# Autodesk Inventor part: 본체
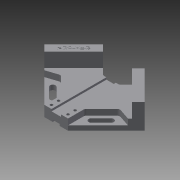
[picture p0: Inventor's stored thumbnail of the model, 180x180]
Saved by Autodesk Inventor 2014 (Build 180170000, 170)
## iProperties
Created: 2019-04
Part Number: 본체
Material: Generic
Document SubType Name: Modeling
Designer: kh
Density: 1 g/cm^3
Appearance: Default
Mass: 222.781 g
Surface Area: 426.536 cm^2
Volume: 222.781 cm^3
Author: kh
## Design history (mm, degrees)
sketch "Sketch1"
  geometry: L1 (0, 84.853)-(-84.853, 0); L2 (-84.853, 0)-(0, -84.853); L3 (0, -84.853)-(84.853, 0); L4 (84.853, 0)-(0, 84.853); L5 (-84.853, 0)-(84.853, 0); L6 (0, 84.853)-(0, -84.853); 3 further points
  constraints: 12 end point, 2 coincident, 2 midpoint, 1 horizontal, 1 perpendicular
  dimensions: "d0" = 120 distance of L1.start L1.end; "d1" = 120 distance of L3.end L1.start; "d2" = 120 distance of L2.end L3.end; "d3" = 120 distance of L1.end L2.end
extrude "Extrusion1" new body sketch "Sketch1" distance "d4" = 18; taper "d5" = 0 deg
sketch "Sketch2"
  geometry: L1 (-8, 18)-(8, 18); L2 (8, 18)-(8, 14.5); L3 (8, 14.5)-(-8, 14.5); L4 (-8, 14.5)-(-8, 18); L5 (-6, 0)-(6, 0); L6 (6, 0)-(6, 3); L7 (6, 3)-(-6, 3); L8 (-6, 3)-(-6, 0); L9 (0, 18)-(-84.853, 18) reference; 2 further points
  constraints: 16 end point, 4 parallel, 2 horizontal, 2 midpoint, 2 perpendicular, 1 coincident
  dimensions: "d6" = 16 distance of L2.end L3.end; "d7" = 3.5 distance of L1.end L2.end; "d8" = 12 distance of L7.end L6.end; "d9" = 3 distance of L6.end L5.end
extrude "Extrusion2" cut sketch "Sketch2" stored distance "d10" = 0; taper "d11" = 0 deg
sketch "Sketch3"
  geometry: L1 (-25, -64.853)-(25, -64.853); L2 (25, -64.853)-(25, -84.853); L3 (25, -84.853)-(-25, -84.853); L4 (-25, -84.853)-(-25, -64.853); L5 (-8, 76.853)-(-84.853, 0) reference; L6 (84.853, 0)-(8, 76.853) reference; L7 (0, 84.853)-(-35.355, 49.497); L8 (-35.355, 49.497)-(0, 14.142); L9 (0, 14.142)-(35.355, 49.497); L10 (35.355, 49.497)-(0, 84.853); L11 (0, -64.853)-(0, 28.147); L12 (0, 28.147)-(14.005, 28.147); L13 (0, 28.147)-(-14.005, 28.147); 3 further points
  constraints: 22 end point, 5 parallel, 3 perpendicular, 3 point on line, 2 midpoint, 1 coincident, 1 collinear, 1 horizontal
  dimensions: "d12" = 20 distance of L1.end L2.end; "d13" = 50 distance of L2.end L3.end; "d14" = 50 distance of L7.start L7.end; "d15" = 50 distance of L8.end L7.end; "d16" = 93 distance of L11.start L11.end
extrude "Extrusion3" cut sketch "Sketch3" stored distance "d17" = 18; taper "d18" = 0 deg
sketch "Sketch4"
  geometry: L1 (84.853, 0)-(35.355, 49.497) reference; L2 (35.355, 49.497)-(84.853, 0); L3 (84.853, 0)-(74.246, -10.607); L4 (74.246, -10.607)-(24.749, 38.891); L5 (24.749, 38.891)-(35.355, 49.497); L6 (-35.355, 49.497)-(-84.853, 0) reference; L7 (-35.355, 49.497)-(-84.853, 0); L8 (-84.853, 0)-(-74.246, -10.607); L9 (-74.246, -10.607)-(-24.749, 38.891); L10 (-24.749, 38.891)-(-35.355, 49.497); 1 further point
  constraints: 16 end point, 6 equal length, 2 perpendicular
  dimensions: "d19" = 15 distance of L1.start L3.end; "d20" = 15 distance of L8.end L6.end
extrude "Extrusion4" join sketch "Sketch4" distance "d21" = 24; taper "d22" = 0 deg
sketch "Sketch5"
  geometry: L1 (-74.246, -10.607)-(-20, -64.853) reference; L2 (-8, 28.147)-(-14.005, 28.147) reference; L3 (-14.005, 28.147)-(-24.749, 38.891) reference; L4 (-20, -64.853)-(-20, -36.569); L5 (-20, -36.569)-(-49.497, -7.071); L6 (-49.497, -7.071)-(-70.711, -14.142); L7 (-84.853, 0)-(-20, -64.853) reference; L8 (-35.355, 49.497)-(-84.853, 0) reference; L9 (0, 0)-(0, 15.349); L10 (-20, -64.853)-(-70.711, -14.142); L11 (20, -64.853)-(70.711, -14.142); L12 (49.497, -7.071)-(70.711, -14.142); L13 (20, -36.569)-(49.497, -7.071); L14 (20, -64.853)-(20, -36.569)
  constraints: 18 end point, 4 symmetric about line, 2 parallel, 1 collinear, 1 perpendicular, 1 point on line
  dimensions: "d25" = 20 distance from line of L1 L5.end; "d26" = 20 distance of L6.end L7.start; "d27" = 30 distance from line of L8 L5.end
extrude "Extrusion5" cut sketch "Sketch5" distance "d28" = 10; taper "d29" = 0 deg
sketch "Sketch6"
  geometry: L1 (-20, -36.569)-(-20, -64.853) reference; L2 (-20, -64.853)-(-70.711, -14.142) reference; L3 (-35.355, 49.497)-(-84.853, 0) reference; L4 (-84.853, 0)-(-20, -64.853) reference; L5 (-49.497, -21.213)-(-32.527, -38.184); L6 (-52.679, -24.395)-(-35.709, -41.366); L7 (-29.345, -35.002)-(-46.315, -18.031); L8 (0, 0)-(0, 13.458); L9 (29.345, -35.002)-(46.315, -18.031); L10 (52.679, -24.395)-(35.709, -41.366); A1 r 4.5 centre (-49.497, -21.213) between (-46.315, -18.031) and (-52.679, -24.395); A2 r 4.5 centre (-32.527, -38.184) between (-35.709, -41.366) and (-29.345, -35.002); A3 r 4.5 centre (49.497, -21.213) between (52.679, -24.395) and (46.315, -18.031); A4 r 4.5 centre (32.527, -38.184) between (29.345, -35.002) and (35.709, -41.366); 1 further point
  constraints: 14 end point, 8 point on circle, 6 symmetric about line, 4 centre point, 4 tangent, 3 parallel, 1 midpoint, 2 other
  dimensions: "d30" = 9 diameter of A2; "d31" = 24 distance of L5.start L5.end; "d32" = 40 distance from line of L3 L5.start; "d33" = 10 distance from line of L2 L5.start
extrude "Extrusion6" cut sketch "Sketch6" stored distance "d34" = 10; taper "d35" = 0 deg
sketch "Sketch7"
  geometry: L1 (6, -64.853)-(20, -64.853) reference; L2 (-14, -46.853)-(14, -46.853); L3 (14, -46.853)-(14, -58.853); L4 (14, -58.853)-(-14, -58.853); L5 (-14, -58.853)-(-14, -46.853); 6 further points
  constraints: 8 end point, 4 coincident, 2 parallel, 1 horizontal, 1 midpoint, 1 perpendicular, 1 vertical alignment
  dimensions: "d36" = 28 distance of L3.end L4.end; "d37" = 12 distance of L2.end L3.end; "d38" = 6 distance between parallel lines of L1 L4
hole "Hole1" sketch "Sketch7" at (-14, -46.853), (-14, -58.853), (14, -58.853), (14, -46.853) diameter "d39" = 4.5; stored, may be unused: countersink angle "d43" = 90 deg, drill point angle "d45" = 118 deg; dims "d40" = 6, "d41" = 8, "d42" = 10, "d44" = 8
sketch "Sketch8"
  geometry: L1 (-35.355, 49.497)-(-84.853, 0) reference; L2 (-24.749, 38.891)-(-35.355, 49.497) reference; L3 (-38.013, 31.988)-(-67.343, 2.658); L4 (-67.343, 2.658)-(-71.589, 6.903); L5 (-71.589, 6.903)-(-42.259, 36.233); L6 (-42.259, 36.233)-(-38.013, 31.988); L7 (-38.013, 31.988)-(-71.589, 6.903); 3 further points
  constraints: 2 end point, 1 coincident, 1 midpoint, 2 other
  dimensions: "d46" = 35 distance from line of L2 point (-54.801, 19.445); "d47" = 7.5 distance from line of L1 point (-54.801, 19.445)
emboss "Emboss1" sketch "Sketch8" dims "d48" = 0.5, "d49" = 0
fillet "Fillet1" dims "d50" = 5
body "Solid1"
